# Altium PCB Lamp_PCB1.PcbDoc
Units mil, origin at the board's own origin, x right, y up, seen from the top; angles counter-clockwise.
Board outline 2450 x 1530 mil, 2 copper layers (Top Layer, Bottom Layer); 65 components, 52 nets, 250 pads, 50 vias.
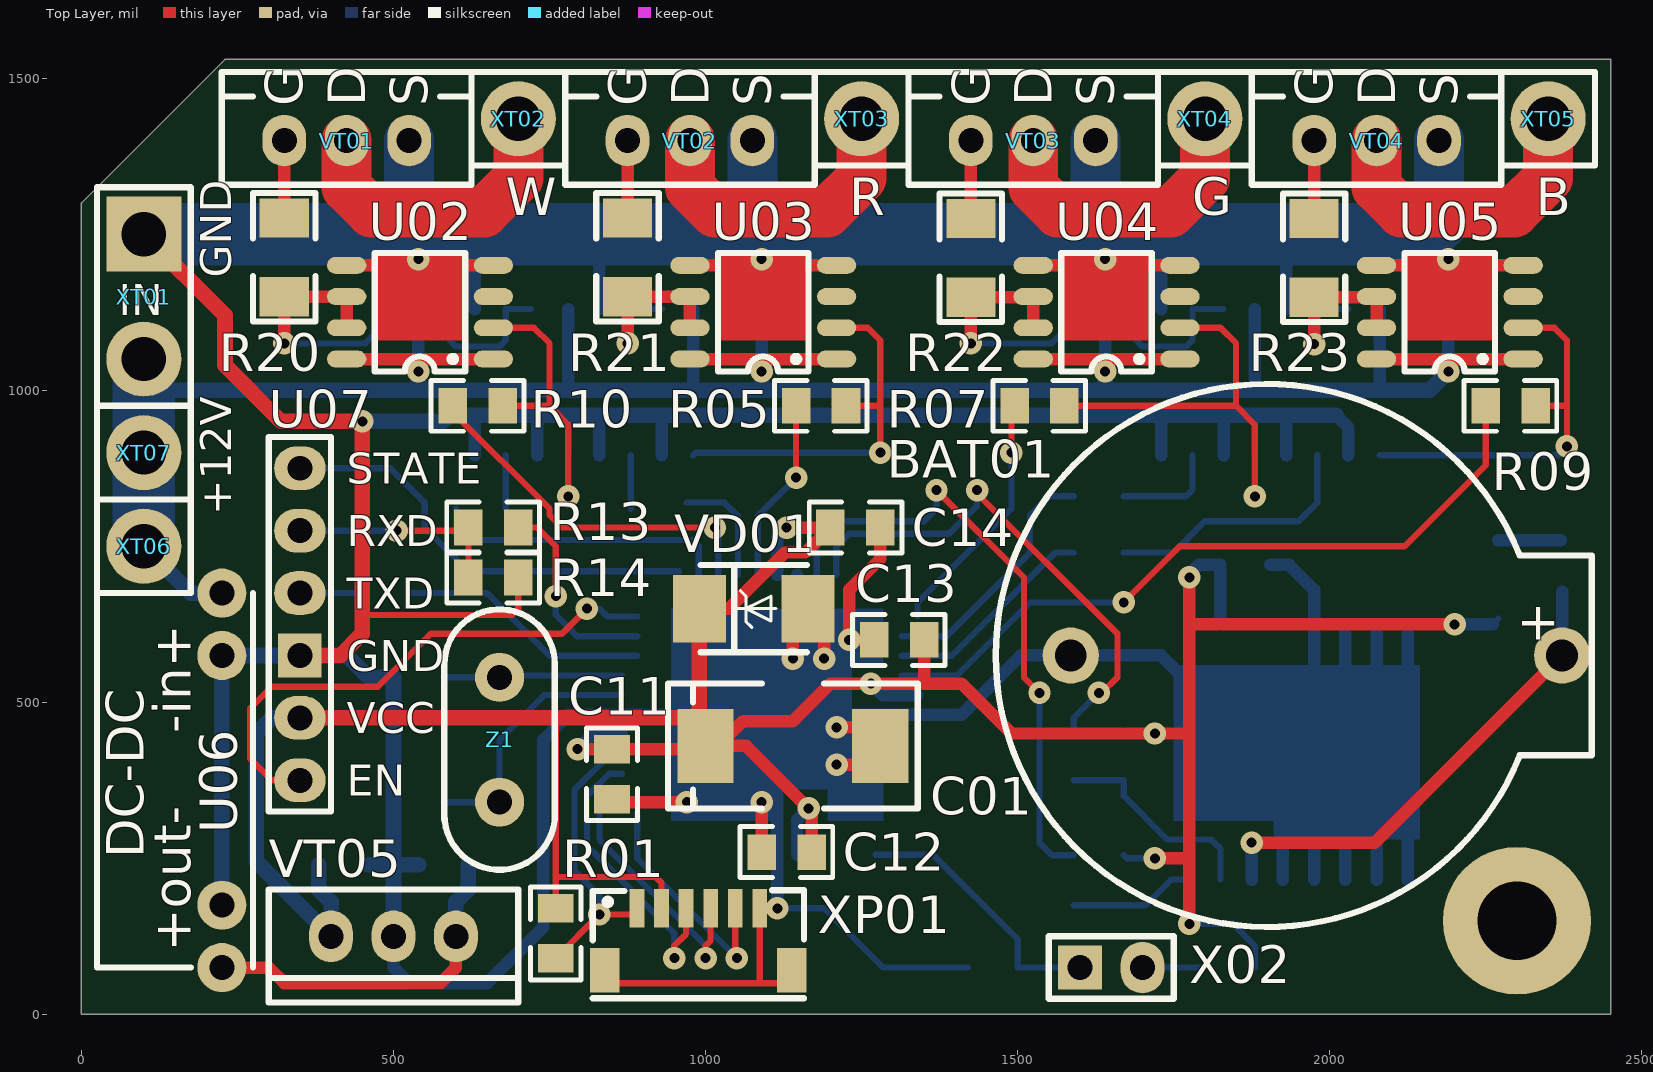
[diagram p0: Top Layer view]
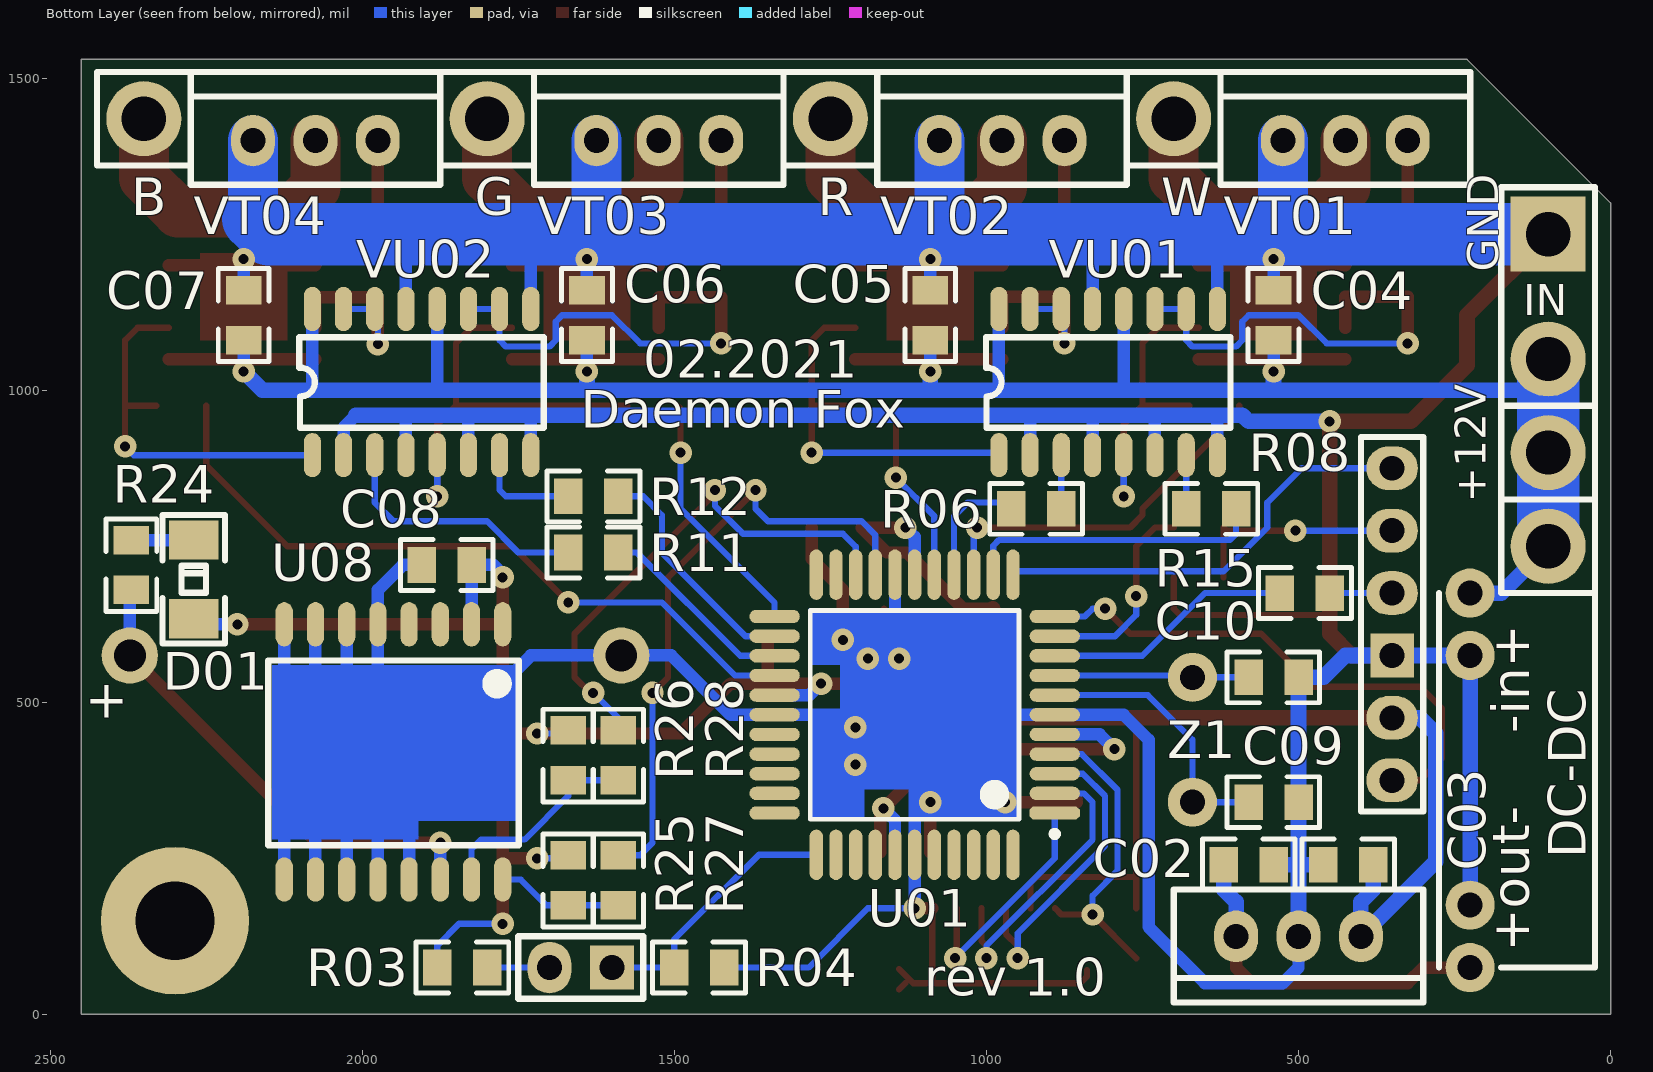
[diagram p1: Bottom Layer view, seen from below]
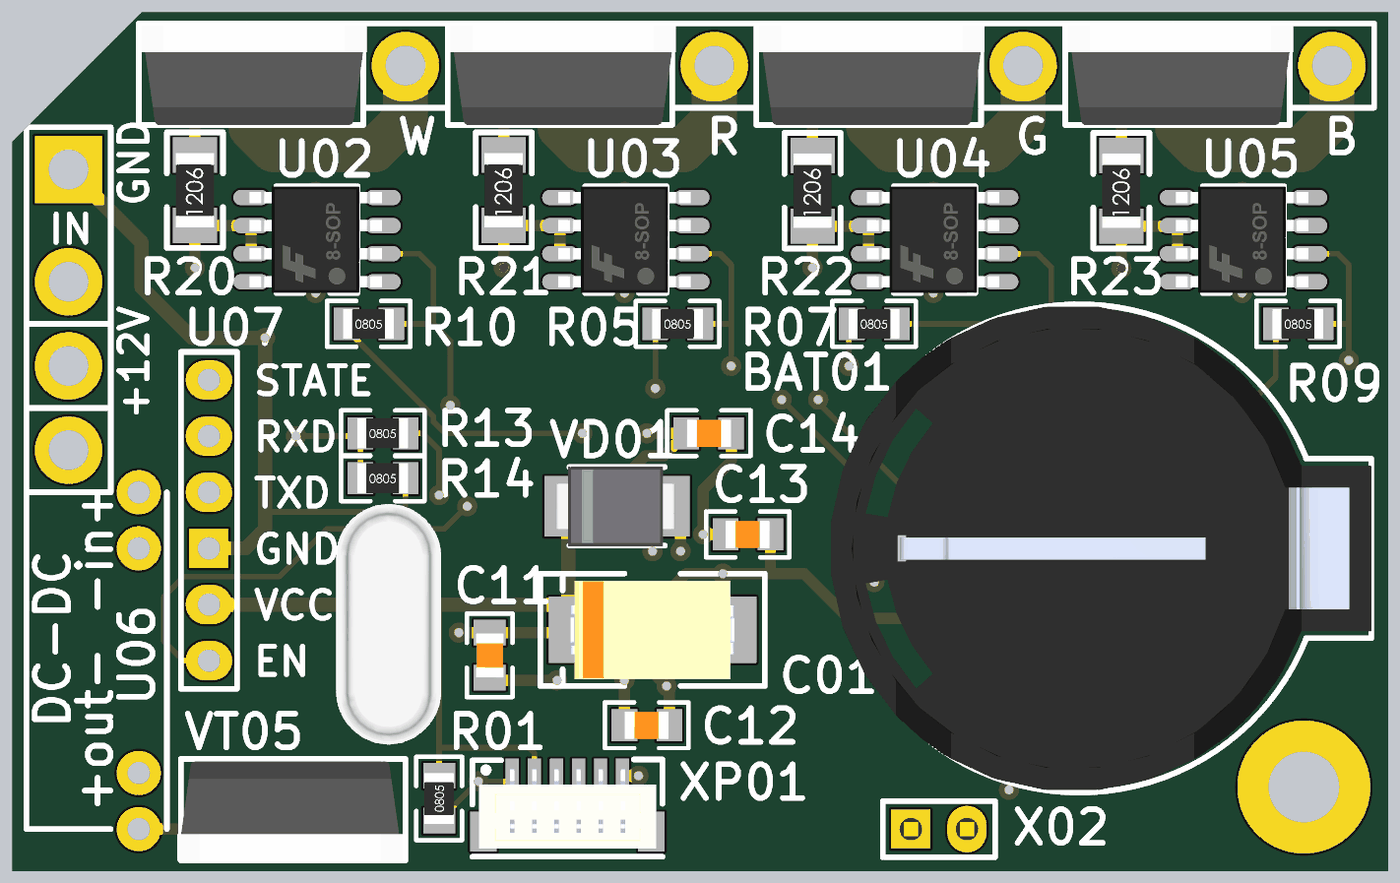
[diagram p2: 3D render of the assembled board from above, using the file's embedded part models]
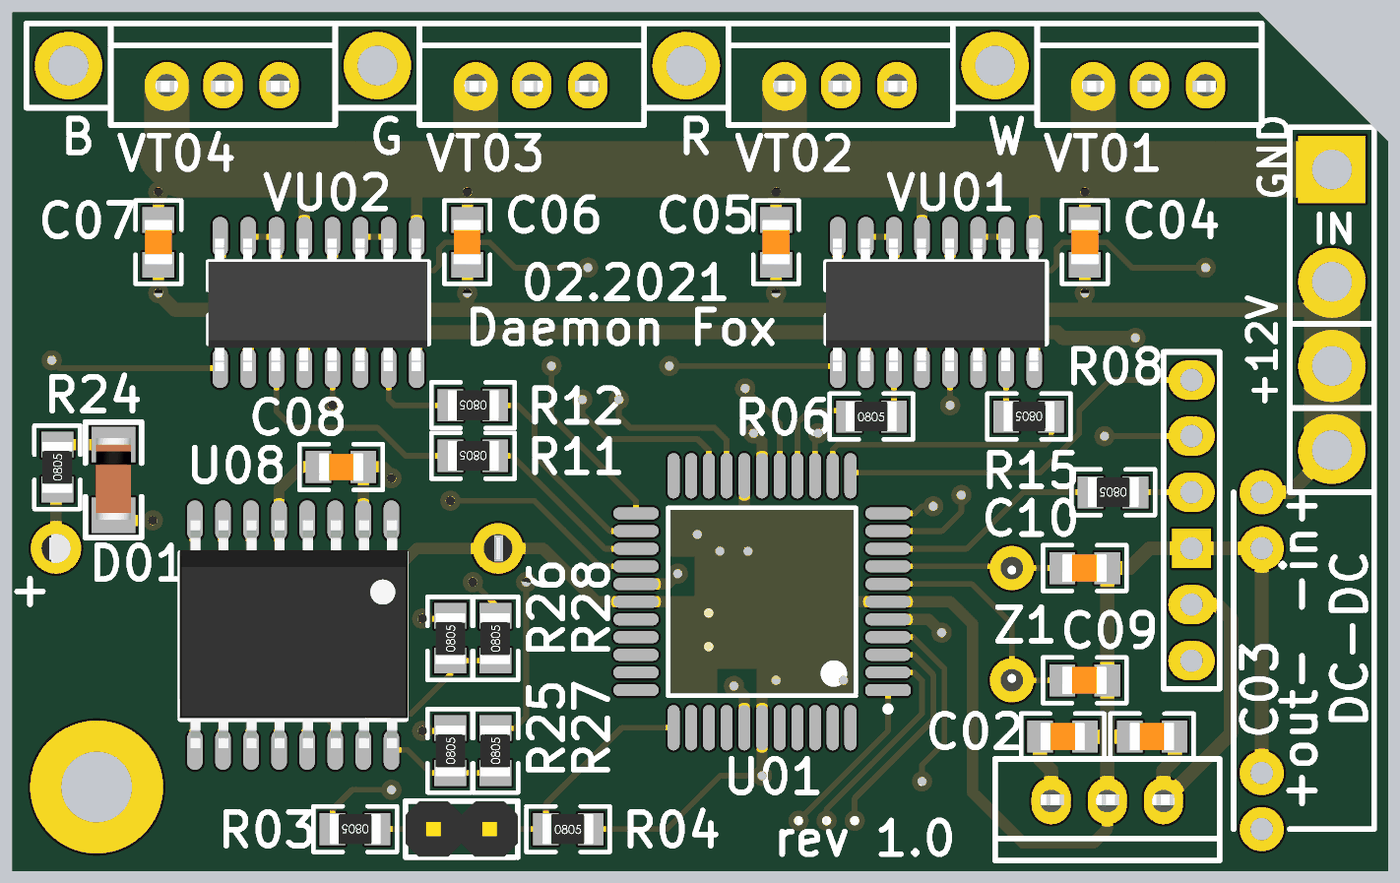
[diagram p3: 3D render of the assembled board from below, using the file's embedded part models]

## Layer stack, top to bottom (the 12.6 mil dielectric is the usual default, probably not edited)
Top Solder: solder mask 0.4, Solder Resist, Dk 3.5
Top Layer: signal copper 1.4
Dielectric 1: dielectric 12.6, FR-4, Dk 4.8
Bottom Layer: signal copper 1.4
Bottom Solder: solder mask 0.4, Solder Resist, Dk 3.5

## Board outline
0,0 0,1300 230,1530 2450,1530 2450,0

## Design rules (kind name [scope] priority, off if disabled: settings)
Clearance [All] p1: gap=10
PolygonConnect [All] p1: connectstyle=Relief reliefconductorwidth=10 reliefentries=4 polygonreliefangle="90 Angle" airgapwidth=10
RoomDefinition Lamp_Sheet1 [InComponentClass('Lamp_Sheet1')] p1: confinementstyle=ConfineIn formatcopy=TRUE lockcomponents=FALSE outline 6045,55 12030,55 12030,745 6045,745
RoutingVias [All] p1: holewidth=28 width=50 viastyle="Through Hole" minholewidth=28 minwidth=50 maxholewidth=28 maxwidth=50
SolderMaskExpansion [All] p1: expansion=4
Width [All] p1: maxlimit=10 minlimit=10 preferedwidth=10
30 further rules are at their usual default settings.

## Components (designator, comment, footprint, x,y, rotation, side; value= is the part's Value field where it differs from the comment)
BAT01 "KLS5-CR2032" KLS5-CR2032 1900,575 r0 top locked
C01 "470uF" cap_tantalum_d 1280,430 r180 top locked
C02 "0.1uF" CAP_0805 540,240 r0 bottom locked
C03 "0.1uF" CAP_0805 460,240 r180 bottom locked
C04 "0.1uF" CAP_0805 540,1160 r270 bottom
C05 "0.1uF" CAP_0805 1090,1160 r270 bottom
C06 "0.1uF" CAP_0805 1640,1160 r270 bottom
C07 "0.1uF" CAP_0805 2190,1160 r270 bottom
C08 "0.1uF" CAP_0805 1825,720 r0 bottom
C09 "22pF" CAP_0805 580,340 r180 bottom locked
C10 "22pF" CAP_0805 580,540 r180 bottom locked
C11 "0.1uF" CAP_0805 850,345 r90 top locked
C12 "0.1uF" CAP_0805 1090,260 r0 top locked
C13 "0.1uF" CAP_0805 1270,600 r0 top
C14 "0.1uF" CAP_0805 1280,780 r180 top
D01 "LL4148" LL4148 2270,643.86 r90 bottom
R01 "10K" RES_0805 760,90 r90 top locked
R03 "10K" RES_0805 1800,75 r0 bottom
R04 "10K" RES_0805 1500,75 r180 bottom
R05 "1.2K" RES_0805 1145,975 r0 top locked
R06 "1.2K" RES_0805 960,810 r180 bottom
R07 "1.2K" RES_0805 1495,975 r0 top locked
R08 "1.2K" RES_0805 600,810 r0 bottom
R09 "1.2K" RES_0805 2250,975 r0 top locked
R10 "1.2K" RES_0805 595,975 r0 top locked
R11 "1.2K" RES_0805 1590,740 r0 bottom
R12 "1.2K" RES_0805 1590,830 r0 bottom
R13 "10K" RES_0805 620,780 r0 top
R14 "10K" RES_0805 620,700 r0 top
R15 "10K" RES_0805 450,675 r0 bottom
R20 "30R" RES_1206 325,1150 r90 top locked
R21 "30R" RES_1206 875,1150 r90 top locked
R22 "30R" RES_1206 1425,1149.02 r90 top locked
R23 "30R" RES_1206 1975,1149.02 r90 top locked
R24 "200R" RES_0805 2370,680 r90 bottom
R25 "4,7K" RES_0805 1670,175 r90 bottom
R26 "4,7K" RES_0805 1670,375 r90 bottom
R27 "560R" RES_0805 1590,175 r90 bottom
R28 "560R" RES_0805 1590,375 r90 bottom
U01 "ATmega16-16AI" My_44A_M 1115,480 r0 bottom locked
U02 "TC4420" ATtiny13A 660,1050 r180 top locked
U03 "TC4420" ATtiny13A 1210,1050 r180 top locked
U04 "TC4420" ATtiny13A 1760,1050 r180 top locked
U05 "TC4420" ATtiny13A 2310,1050 r180 top locked
U06 "Mini-360" Mini-360 225,75 r90 top locked
U07 "HC-06" HC-05/06 350,875 r270 top locked
U08 "DS3231_DUP" DS3231 1775,625 r0 bottom locked
VD01 "SMBJ5.0A" SMBJ5.0A 1164,650 r180 top locked
VT01 "IRF530" "IRF530 - DUP" 525,1400 r90 top locked
VT02 "IRF530" "IRF530 - DUP" 1075,1400 r90 top locked
VT03 "IRF530" "IRF530 - DUP" 1625,1400 r90 top locked
VT04 "IRF530" "IRF530 - DUP" 2175,1400 r90 top locked
VT05 "L7805" L7805 400,125 r270 top locked
VU01 "TLP281-4" TLP281-4 609.1,940 r90 bottom locked
VU02 "TLP281-4" TLP281-4 1709.1,940 r90 bottom locked
X02 "PLS-2" "PLS-2 - DUP" 1600,75 r0 top
XP01 "JST SH 1.0mm_6P" "JST SH 1.0mm 6P" 838.8,70.6 r0 top locked
XT01 "LED_12v_IN" "LED_12v_IN - DUP" 100,1250 r270 top locked
XT02 "LED_12v_1" LED_12v_1 700,1435 r90 top locked
XT03 "LED_12v_1" LED_12v_1 1250,1435 r90 top locked
XT04 "LED_12v_1" LED_12v_1 1800,1435 r90 top locked
XT05 "LED_12v_1" LED_12v_1 2350,1435 r90 top locked
XT06 "LED_12v_1" LED_12v_1 100,750 r0 top locked
XT07 "LED_12v_1" LED_12v_1 100,900 r0 top locked
Z1 "16MHz" QUARTZ 670,340 r180 top locked

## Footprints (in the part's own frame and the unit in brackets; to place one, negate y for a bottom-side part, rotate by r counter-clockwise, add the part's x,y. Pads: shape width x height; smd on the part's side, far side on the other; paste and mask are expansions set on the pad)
ATtiny13A [mil] "ATtiny13A SOP-8"
  oval 63x27 smd: 1(0,0) 2(0,-50) 3(0,-100) 4(0,-150) 5(235,-150) 6(235,-100) 7(235,-50) 8(235,0)
  silkscreen extent 45,-170 190,20, body extent 2,-170 238,20, height 67
CAP_0805 [mm] "CAP 0805 by DFox"
  rect 1.16x1.45 smd: 1(0,0) 2(2.032,0)
  silkscreen extent -0.88,-1.03 2.89,1.04, body extent 0,-0.63 2,0.63, height 0.8
cap_tantalum_d [mil] "capacitor tantalum, Type D"
  rect 90x118 smd: 1(280,0)
  rect 90x118.5 smd: 2(0,0)
  silkscreen extent -60,-100 340,100, body extent -6,-88 286,88, height 118
DS3231 [mm] "Часы реального времени, SO-16W"
  oval 0.7x1.8 smd: 1(0,0) 2(1.27,0) 3(2.54,0) 4(3.81,0) 5(5.08,0) 6(6.35,0) 7(7.62,0) 8(8.89,0) 9(8.89,10.389) 10(7.62,10.389) 11(6.35,10.389) 12(5.08,10.389) 13(3.81,10.389) 14(2.54,10.389) 15(1.27,10.389) 16(0,10.389)
  silkscreen extent -0.66,1.47 9.55,8.99, body extent -0.75,0 9.58,10.31, height 2.48
HC-05/06 [mil] "Bluetooth модуль HC-06 slave; HC-05 master/slave."
  oval 70x82.68 hole 40: 1(0,0) 2(100,0) 3(200,0) 5(400,0) 6(500,0)
  rect 70x70 hole 40: 4(300,0)
  silkscreen extent -50,-50 550,50
"IRF530 - DUP" [mil] "IRF530 N-канал, 100в, 15А, TO-220AB"
  oval 82.68x70 hole 40: 1(0,200) 2(0,100) 3(0,0)
  silkscreen extent -71,-100 110,300, body extent -71,-106 106,295, height 869
"JST SH 1.0mm 6P" [mm] "JST- BM06B-SRSS-TB, 6P"
  rect 0.6x1.55 smd: 1(1.3,2.525) 2(2.3,2.525) 3(3.3,2.525) 4(4.3,2.525) 5(5.3,2.525)
  rect 0.599x1.549 smd: 6(6.301,2.524)
  rect 1.201x1.798 smd: 7(7.6,0)
  rect 1.199x1.798 smd: 8(0,0)
  silkscreen extent -0.5,-1.14 8.1,3.26, body extent -0.19,-0.76 7.81,2.84, height 4.25
KLS5-CR2032 [mil] "Батарейный отсек на 1xCR2032"
  round 90 hole 51.2: 1(472.48,0) 2(-314.92,0)
  silkscreen extent -435,-435 520,435, body extent -445,-433 520,433, height 335
L7805 [mil] "Стабилизатор напряжения +5В, 1.5А, TO-220"
  oval 82.68x70 hole 40: 1(0,200) 2(0,100) 3(0,0)
  silkscreen extent -75,-100 106,300, body extent -71,-106 106,295, height 869
LED_12v_1 [mm]
  round 3.054 hole 1.8: 1(0,0)
  silkscreen extent -1.91,-1.91 1.91,1.91
"LED_12v_IN - DUP" [mm]
  round 3.054 hole 1.8: 1(5.08,0)
  rect 3.054x3.054 hole 1.8: 2(0,0)
  silkscreen extent -1.91,-1.91 6.98,1.91
LL4148 [mm] "Diod SOD80 200mA 100V"
  rect 1.6x2 smd: 1(-0.25,0) 2(2.95,0)
  silkscreen extent -1.26,-1.27 3.97,1.27, body extent -0.45,-0.8 3.25,0.8, height 1.61
Mini-360 [mm] "Mini360, понижающий модуль, с 4,75 в-23 в до 1 В-17 в, 17x11x3,8 мм"
  round 2 hole 1.016: 1(15.24,0) 2(0,0) 3(2.54,0) 3(12.7,0)
  silkscreen extent 0,-1.27 15.24,5.08
My_44A_M [mm]
  oct 2.05x0.544 smd: 1(-5.7,4)
  oval 2.05x0.544 smd: 2(-5.7,3.2) 3(-5.7,2.4) 4(-5.7,1.6) 5(-5.7,0.8) 6(-5.7,0) 7(-5.7,-0.8) 8(-5.7,-1.6) 9(-5.7,-2.4) 10(-5.7,-3.2) 11(-5.7,-4) 23(5.7,-4) 24(5.7,-3.2) 25(5.7,-2.4) 26(5.7,-1.6) 27(5.7,-0.8) 28(5.7,0) 29(5.7,0.8) 30(5.7,1.6) 31(5.7,2.4) 32(5.7,3.2) 33(5.7,4)
  oval 0.544x2.05 smd: 12(-4,-5.7) 13(-3.2,-5.7) 14(-2.4,-5.7) 15(-1.6,-5.7) 16(-0.8,-5.7) 17(0,-5.7) 18(0.8,-5.7) 19(1.6,-5.7) 20(2.4,-5.7) 21(3.2,-5.7) 22(4,-5.7) 34(4,5.7) 35(3.2,5.7) 36(2.4,5.7) 37(1.6,5.7) 38(0.8,5.7) 39(0,5.7) 40(-0.8,5.7) 41(-1.6,5.7) 42(-2.4,5.7) 43(-3.2,5.7) 44(-4,5.7)
  silkscreen extent -5.82,-4.25 4.25,4.97, body extent -5,-5 5,5, height 1.2
"PLS-2 - DUP" [mil]
  rect 70x70 hole 40: 1(0,0)
  oval 70x82.68 hole 40: 2(100,0)
  silkscreen extent -50,-50 150,50, body extent -50,-49 150,49, height 335
QUARTZ [mm] "quartz crystal resonator"
  round 2 hole 1.016: 1(0,0) 2(0,-5.08)
  silkscreen extent -2.25,-7.84 2.25,2.75, body extent -2.33,-7.99 2.33,2.91, height 13.5
RES_0805 [mm] "RES 0805 by DFox"
  rect 1.16x1.45 smd: 1(0,0) 2(2.032,0)
  silkscreen extent -0.88,-1.03 2.89,1.04, body extent -0.15,-0.67 2.15,0.67, height 0.76
RES_1206 [mil] "RES 1206 by DFox"
  rect 63x78.74 smd: 1(0,0) 2(125.98,0)
  silkscreen extent -40,-50 166,50, body extent -3,-34 129,34, height 33
SMBJ5.0A [mil] "TVS SUPRESSOR 5V, [DO-214AA]"
  rect 85x108 smd: 1(0,0) 2(174,0)
  silkscreen extent 2,-70 172,70, body extent -16,-71 196,71, height 93
TLP281-4 [mm] "Оптопара транзисторная [SOP-16]"
  oval 1.8x0.7 smd: 1(-1.118,9.421) 2(-1.118,8.151) 3(-1.118,6.881) 4(-1.118,5.611) 5(-1.118,4.341) 6(-1.118,3.071) 7(-1.118,1.801) 8(-1.118,0.531) 9(4.826,0.531) 10(4.826,1.801) 11(4.826,3.071) 12(4.826,4.341) 13(4.826,5.611) 14(4.826,6.881) 15(4.826,8.151) 16(4.826,9.421)
  silkscreen extent 0,0 3.68,9.95, body extent -1.25,0.05 4.75,9.95, height 1.4

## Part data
BAT01: "Батарейный отсек на 1xCR2032"
C01: library part "470uF 10v_D", "CAPACITOR Tantalium Type D 470uF 10v"
C02 C03 C04 C05 C06 C07 C08 C09 C10 C11 C12 C13 C14: library part "CAP 0805", "CAP 0805 SMD"
D01: "Diod SOD80 200mA 100V"
R01 R03 R04 R05 R06 R07 R08 R09 R10 R11 R12 R13 R14 R15 R24 R25 R26 R27 R28: library part "RES 0805", "RES 0805"
R20 R21 R22 R23: library part "RES 1206", "RES 1206 by DFox"
U01: "AVR 16K Bytes of In-System Programmable Flash Memory"
U02 U03 U04 U05: "HIGH-SPEED MOSFET  DRIVERS"
U06: "Mini360, понижающий модуль, с 4,75 в-23 в до 1 В-17 в, 17x11x3,8 мм"
U07: library part HC-05/06, "Bluetooth модуль HC-06 slave; HC-05 master/slave."
U08: "Часы реального времени"
VD01: "Защитный диод, 500Вт, 5В, [DO-214AA]"
VT01 VT02 VT03 VT04: "IRF530 N-канал, 100в, 15А, TO-220AB"
VT05: "Стабилизатор напряжения +5В, 1.5А, TO-220"
XP01: "JST SH 1.0mm 6P"
Z1: library part QUARTZ, "quartz crystal resonator"

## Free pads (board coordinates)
  round 237 hole 126: 8(2300,150)

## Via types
v1: diameter 36, hole 16, Top Layer to Bottom Layer, tented both sides, 50 vias

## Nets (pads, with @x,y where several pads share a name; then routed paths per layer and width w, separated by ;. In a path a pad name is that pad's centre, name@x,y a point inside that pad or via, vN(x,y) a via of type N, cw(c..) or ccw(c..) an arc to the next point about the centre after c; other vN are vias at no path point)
GND: BAT01.2 C01.2 C02.1 C03.1 C04.1 C05.1 C06.1 C07.1 C08.2 C09.2 C10.2 C11.1 C12.1 C13.1 C14.1 R04.2 R14.2 U01.6 U01.18 U01.28 U01.39 U02.4 U02.5 U03.4 U03.5 U04.4 U04.5 U05.4 U05.5 U06.3 U07.4 U08.5 U08.6 U08.7 U08.8 U08.9 U08.10 U08.11 U08.12 U08.13 VD01.1 VT01.3 VT02.3 VT03.3 VT04.3 VT05.2 VU01.2 VU01.4 VU01.6 VU01.8 VU01.9 VU01.13 VU02.2 VU02.4 VU02.6 VU02.8 VU02.9 VU02.13 XP01.6 XP01.7 XP01.8 XT01.2 | length 13135.7
  Top Layer w10: 450,640 690,640 700,650 R14.2 ; XP01.8 838.8,61.2 850,50 1086.87,50 ; C11.1 C11.1@855,340 ; XP01.6 1086.87,50 ; XP01.7@1130,50 XP01.7@1140,40 ; XP01.7@1140,72.58 XP01.7 1117.42,50 1086.87,50 ; VD01.1@1140,626 VD01.1 VD01.1@1190,624 ; C01.2@1250,400 C01.2 C01.2@1250,460
  Top Layer w20: U02.5 U02.4 ; C11.1@855,340 v1(970,340) ; U03.5 U03.4 ; XP01.6 v1(1115,170) ; C12.1 v1(1090,340) ; v1(1140,570) VD01.1@1140,626 ; v1(1190,570) VD01.1@1190,624 ; v1(1210,400) C01.2@1250,400 ; v1(1210,460) C01.2@1250,460 ; C13.1 v1(1230,600) 1230,680 1280,730 C14.1 ; U04.5 U04.4 ; U05.5 U05.4
  Top Layer w25: XT01.2 230,1120 230,1040 320,950 v1(450,950) 450,640 450,610 415,575 U07.4
  Bottom Layer w10: 624,1250 630,1244 ; 825,1250 830,1245 ; v1(1115,170) 1190,170 1285,75 R04.2 ; 1725,1250 1730,1245
  Bottom Layer w20: VT05.2 500,75 525,50 650,50 740,140 740,440 780,480 U01.6@865.59,480 ; C04.1 v1(540,1210) ; VU01.8 630,960 ; VU01.9 630,1244 ; VU01.6 730,960 ; VU01.4 830,960 ; VU01.13 830,1245 ; U01.6@869.09,480 960,480 ; VU01.2 930,960 ; C05.1 v1(1090,1210) ; v1(1115,170) U01.39 1115,330 ; 1146.5,631.5 U01.18 ; 1260,480 U01.28 1410,480 1505,575 BAT01.2 1730,575 1762.5,542.5 ; C06.1 v1(1640,1210) ; VU02.8 1730,960 ; VU02.9 1730,1245 ; VU02.6 1830,960 ; C08.2 1935,720 1975,680 U08.5 1975,525 ; U08.13 1925,315 ; VU02.4 1930,960 ; VU02.13 1930,1250 ; U08.12 1975,315 ; 2010,960 2030,940 VU02.2 ; U08.11 2025,315 ; 2025,525 U08.6 ; U08.10 2075,315 ; 2075,525 U08.7 ; U08.9 2125,315 ; 2125,525 U08.8 ; C07.1 v1(2190,1210)
  Bottom Layer w25: U06.3@225,175 225,575 U07.4 425,575 460,540 C10.2 C09.2 500,240 ; v1(450,950) 580,950 590,960 630,960 730,960 830,960 930,960 1730,960 1830,960 1930,960 2010,960 ; C03.1 500,240 ; VT05.2 500,240 ; C02.1 500,240
  Bottom Layer w80: 525,1250 VT01.3 ; 1075,1250 VT02.3 ; 1625,1250 VT03.3 ; 2175,1275 VT04.3
  Bottom Layer w100: XT01.2 525,1250 ; 540,1250 624,1250 825,1250 1075,1250 1625,1250 1725,1250 1930,1250 2150,1250 2175,1275
NetBAT01_1: BAT01.1 R24.1 U08.14 | length 786.8
  Top Layer w20: v1(1875,275) 2072.48,275 BAT01.1
  Bottom Layer w10: R24.1 R24.1@2372.48,677.52
  Bottom Layer w20: U08.14 v1(1875,275) ; BAT01.1 R24.1@2372.48,677.52
NetC01_1: C01.1 C03.2 C08.1 C11.2 C12.2 C13.2 C14.2 D01.1 R01.2 R03.2 R25.2 R26.2 U01.5 U01.17 U01.27 U01.38 U07.5 U08.2 VD01.2 VT05.3 XP01.2 | length 5520.2
  Top Layer w10: R01.2 760,220 ; 760,475 760,220 ; XP01.2 929.37,210.63 920,220 760,220 ; C01.1@990,440 C01.1 ; C01.1@995,425 C01.1 ; C01.1@1020,430 C01.1 ; v1(1165,330) v1@1170,325
  Top Layer w20: v1(795,425) C11.2 C01.1@995,425 ; VD01.2 1037.5,650 1127.5,740 1160,740 C14.2 v1(1130,780) ; v1(1165,330) 1065,430 1020,430 1060,470 1140,470 1200,530 v1(1265,530) 1350,530 ; C12.2 v1@1170,325 ; C13.2 1350,530 ; v1(1720,250) 1775,250 ; v1(1775,145) 1775,250 ; v1(1775,700) 1775,625 ; v1(2200,625) 1775,625 ; 1350,530 1410,530 1490,450 v1(1720,450) 1775,450 ; 1775,250 1775,450 ; 1775,450 1775,625
  Top Layer w25: U07.5 760,475 C01.1@980,475 ; C01.1@990,440 VD01.2
  Bottom Layer w10: R25.2 1675,250 v1(1720,250) ; R26.2 1675,450 v1(1720,450) ; v1(1775,145) 1845,145 1880,110 R03.2 ; v1(1775,700) v1@1775,705 ; D01.1@2260.98,625 D01.1
  Bottom Layer w20: v1(795,425) 818.5,448.5 U01.5@865.59,448.5 ; U01.17 1115,765 v1(1130,780) ; U01.38 1146.5,311.5 v1(1165,330) ; v1(1265,530) 1283.5,511.5 U01.27 ; v1@1775,705 1790,720 C08.1 U08.2 ; v1(2200,625) D01.1@2260.98,625
  Bottom Layer w25: U07.5 305,475 280,450 280,245 VT05.3 400,180 380,200 C03.2
NetC02_2: C02.2 U06.2 VT05.1 | length 569
  Top Layer w20: U06.2 300,75 325,50 575,50 600,75 VT05.1
  Bottom Layer w25: VT05.1 600,180 620,200 C02.2
NetC04_2: C04.2 C05.2 C06.2 C07.2 U02.1 U02.8 U03.1 U03.8 U04.1 U04.8 U05.1 U05.8 U06.1 VU01.12 VU01.16 VU02.12 VU02.16 XT01.1 XT06.1 XT07.1 | length 4296.8
  Top Layer w20: U02.8 U02.1 ; U03.8 U03.1 ; U04.8 U04.1 ; U05.8 U05.1
  Bottom Layer w10: 225,995 230,1000 ; 775,1000 780,1005 ; 975,1000 980,1005 ; 1875,1000 1880,1005
  Bottom Layer w20: v1(540,1030) C04.2 ; 780,1005 VU01.12 ; 980,1005 VU01.16 ; v1(1090,1030) C05.2 ; v1(1640,1030) C06.2 ; 1880,1005 VU02.12 ; 2080,1000 VU02.16 ; v1(2190,1030) C07.2
  Bottom Layer w25: XT06.1 175,675 U06.1 ; XT01.1@125,1000 230,1000 540,1000 ; v1(540,1030) 540,1000 ; v1(1090,1030) 1090,1000 ; v1(1640,1030) 1640,1000 ; v1(2190,1030) 2160,1000 2080,1000 1875,1000 1640,1000 ; 540,1000 775,1000 975,1000 1090,1000 ; 1090,1000 1640,1000
  Bottom Layer w100: XT06.1 XT07.1 XT01.1
NetC09_1: C09.1 U01.7 Z1.1 | length 415.2
  Bottom Layer w10: C09.1 Z1.1 670,440 741.5,511.5 U01.7@865.59,511.5
NetC10_1: C10.1 U01.8 Z1.2 | length 286.8
  Bottom Layer w10: C10.1 Z1.2 672.99,542.99 U01.8@865.59,542.99
NetD01_2: D01.2 R24.2 | length 100
  Bottom Layer w20: D01.2 R24.2
NetR01_1: R01.1 U01.4 XP01.1 | length 478.9
  Top Layer w10: R01.1 v1(830,160) 880,160 XP01.1
  Bottom Layer w10: v1(830,160) 830,190 790,230 790,360 847.01,417.01 U01.4@865.59,417.01
NetR03_1: R03.1 X02.2 | length 100
  Bottom Layer w10: X02.2 R03.1
NetR04_1: R04.1 U01.34 X02.1 | length 428.7
  Bottom Layer w10: U01.34 1364.41,255.59 1500,120 R04.1 X02.1
NetR05_1: R05.1 U01.16 | length 300.2
  Top Layer w10: v1(1145,860) 1145,965 1150,970 R05.1
  Bottom Layer w10: U01.16 1083.5,798.5 v1(1145,860)
NetR05_2: R05.2 U03.2 VU01.1 | length 614.9
  Top Layer w10: U03.2 1260,1100 1280,1080 1280,975 ; R05.2 1280,975 ; v1(1280,900) 1280,975
  Bottom Layer w10: VU01.1 984,900 v1(1280,900)
NetR06_1: R06.1 U01.15 | length 184.7
  Bottom Layer w10: R06.1@970,820 1030,820 1052.01,797.99 U01.15
NetR06_2: R06.2 VU01.3 | length 86
  Bottom Layer w10: R06.2 VU01.3
NetR07_1: R07.1 U01.23 | length 401.7
  Top Layer w10: v1(1490,900) 1490,970 R07.1
  Bottom Layer w10: U01.23 1339.41,660 ; 1340,660 1490,810 v1(1490,900)
NetR07_2: R07.2 U04.2 VU02.5 | length 698.8
  Top Layer w10: R07.2 1850,975 ; U04.2 1825,1100 1850,1075 1850,975 ; v1(1880,830) 1880,945 1850,975
  Bottom Layer w10: v1(1880,830) VU02.5
NetR08_1: R08.1 U01.13 | length 483.5
  Bottom Layer w10: R08.1 600,770 610,760 980,760 989.02,750.98 U01.13
NetR08_2: R08.2 VU01.7 | length 86
  Bottom Layer w10: R08.2 VU01.7
NetR09_1: R09.1 U01.26 | length 1170.2
  Top Layer w10: v1(1670,660) 1760,750 2120,750 2250,880 R09.1
  Bottom Layer w10: U01.26@1314.41,542.99 U01.26 1402.99,542.99 1520,660 v1(1670,660)
NetR09_2: R09.2 U05.2 VU02.1 | length 604.1
  Top Layer w10: U05.2 2360,1100 2380,1080 2380,975 ; R09.2 2380,975 ; v1(2380,910) 2380,975
  Bottom Layer w10: VU02.1 2366,896 v1(2380,910)
NetR10_1: R10.1 U01.14 | length 590.4
  Top Layer w10: R10.1 595,965 750,810 750,800 770,780 v1(1015,780)
  Bottom Layer w10: v1(1015,780) 1020.51,774.49 U01.14
NetR10_2: R10.2 U02.2 VU01.5 | length 498.8
  Top Layer w10: U02.2 725,1100 750,1075 750,975 ; R10.2 750,975 ; v1(780,830) 780,945 750,975
  Bottom Layer w10: v1(780,830) VU01.5
NetR11_1: R11.1 U01.25 | length 344.1
  Bottom Layer w10: U01.25@1314.41,574.49 U01.25 1394.49,574.49 1560,740 R11.1
NetR11_2: R11.2 VU02.3 | length 419.1
  Bottom Layer w10: R11.2 1750,740 1800,790 1950,790 1980,820 VU02.3
NetR12_1: R12.1 U01.24 | length 403.5
  Bottom Layer w10: U01.24@1314.41,605.98 U01.24 1385.98,605.98 1520,740 1520,800 1550,830 R12.1
NetR12_2: R12.2 VU02.7 | length 170.1
  Bottom Layer w10: R12.2 1770,830 1780,840 VU02.7
NetR13_1: R13.1 R14.1 U07.2 | length 352.1
  Top Layer w10: v1(505,775) 615,775 R13.1 R14.1
  Bottom Layer w10: U07.2 v1(505,775)
NetR13_2: R13.2 U01.10 | length 327.1
  Top Layer w10: R13.2 730,780 760,750 v1(760,670)
  Bottom Layer w10: v1(760,670) 760,640 794.02,605.98 U01.10
NetR15_1: R15.1 U07.3 | length 100
  Bottom Layer w10: U07.3 R15.1
NetR15_2: R15.2 U01.9 | length 402.2
  Bottom Layer w10: R15.2 650,675 750.51,574.49 U01.9
NetR20_1: R20.1 U02.6 U02.7 VU01.10 VU01.11 | length 731.1
  Top Layer w20: v1(325,1075) R20.1 U02.6 U02.7
  Bottom Layer w10: v1(325,1075) 455,1075 500,1120 580,1120 590,1110 590,1080 600,1070 670,1070 680,1080 VU01.10 VU01.11@720,1130
NetR20_2: R20.2 VT01.1 | length 124
  Top Layer w20: R20.2 VT01.1
NetR21_1: R21.1 U03.6 U03.7 VU01.14 VU01.15 | length 339.1
  Top Layer w20: v1(875,1075) R21.1 U03.6 U03.7
  Bottom Layer w10: v1@870,1080 v1(875,1075) 875,1125 VU01.14 VU01.15
NetR21_2: R21.2 VT02.1 | length 124
  Top Layer w20: R21.2 VT02.1
NetR22_1: R22.1 U04.6 U04.7 VU02.10 VU02.11 | length 739.5
  Top Layer w10: R22.1 R22.1@1425,1150 ; U04.6@1524.02,1149.02 U04.6@1525,1148.04
  Top Layer w20: v1(1425,1075) R22.1 U04.6@1524.02,1149.02 ; U04.7 U04.6@1525,1148.04
  Bottom Layer w10: v1(1425,1075) 1555,1075 1600,1120 1680,1120 1690,1110 1690,1080 1700,1070 1770,1070 1780,1080 VU02.10 VU02.11
NetR22_2: R22.2 VT03.1 | length 125
  Top Layer w20: R22.2 VT03.1
NetR23_1: R23.1 U05.6 U05.7 VU02.14 VU02.15 | length 323.4
  Top Layer w10: U05.6@2074.02,1149.02 U05.6@2075,1148.04
  Top Layer w20: v1(1975,1074.02) R23.1 U05.6@2074.02,1149.02 ; U05.7 U05.6@2075,1148.04
  Bottom Layer w10: v1(1975,1074.02) VU02.14@1975,1124.02 ; VU02.14 VU02.15
NetR23_2: R23.2 VT04.1 | length 125
  Top Layer w20: R23.2 VT04.1
NetR25_1: R25.1 R27.1 U08.16 | length 207.6
  Bottom Layer w10: R27.1 R25.1 1705,175 1746,216 U08.16 U08.16@1771,220
NetR26_1: R26.1 R28.1 U08.15 | length 344.2
  Bottom Layer w10: R28.1 R26.1 1670,350 1740,280 1810,280 1825,265 U08.15
NetR27_2: R27.2 U01.19 | length 1012.8
  Top Layer w10: v1(1370,840) 1510,700 1510,540 v1(1535,515) v1@1535,528.19
  Bottom Layer w10: U01.19 1177.99,767.99 1200,790 1350,790 1370,810 v1(1370,840) ; v1(1535,515) 1535,275 1555,255 R27.2
NetR28_2: R28.2 U01.20 | length 839.9
  Top Layer w10: v1(1435,840) 1430,840 1660,610 1660,540 1635,515 v1(1630,515)
  Bottom Layer w10: U01.20 1209.49,749.49 1230,770 1390,770 1435,815 v1(1435,840) ; R28.2 1590,475 v1(1630,515)
NetU01_1: U01.1 XP01.5 | length 365.3
  Top Layer w10: XP01.5 1047.48,92.52 v1(1050,90)
  Bottom Layer w10: U01.1 890.59,250 v1@1040.3,100.3
NetU01_2: U01.2 XP01.4 | length 445.2
  Top Layer w10: v1(1000,90) 1000,110 1008.11,118.11 XP01.4
  Bottom Layer w10: U01.2@865.59,354.02 844.02,354.02 830,340 830,280 1000,110 v1(1000,90)
NetU01_3: U01.3 XP01.3 | length 476.1
  Top Layer w10: v1(950,90) 950,110 968.74,128.74 XP01.3
  Bottom Layer w10: U01.3@865.59,385.51 845.51,385.51 810,350 810,270 950,130 v1(950,90)
NetU01_11: U01.11 U07.6 | length 866.5
  Top Layer w10: U07.6 305,375 270,410 270,490 305,525 475,525 560,610 770,610 v1(810,650)
  Bottom Layer w10: v1(810,650) 830,650 842.52,637.48 U01.11
NetU01_12: U01.12 U07.1 | length 699.3
  Bottom Layer w10: U07.1 495,875 550,820 550,780 620,710 U01.12@957.52,710
NetVT01_2: VT01.2 XT02.1 | length 484.4
  Top Layer w80: VT01.2 425,1325 465,1285 645,1285 700,1340 XT02.1
NetVT02_2: VT02.2 XT03.1 | length 484.4
  Top Layer w80: VT02.2 975,1325 1015,1285 1195,1285 1250,1340 XT03.1
NetVT03_2: VT03.2 XT04.1 | length 484.4
  Top Layer w80: VT03.2 1525,1325 1565,1285 1745,1285 1800,1340 XT04.1
NetVT04_2: VT04.2 XT05.1 | length 484.4
  Top Layer w80: VT04.2 2075,1325 2115,1285 2295,1285 2350,1340 XT05.1
pads on no net: U01.21 U01.22 U01.29 U01.30 U01.31 U01.32 U01.33 U01.35 U01.36 U01.37 U01.40 U01.41 U01.42 U01.43 U01.44 U02.3 U03.3 U04.3 U05.3 U08.1 U08.3 U08.4

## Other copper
Top Layer:
  region net GND: 470,1220 470,1080 610,1080 610,1220
  region net GND: 2120,1220 2120,1080 2260,1080 2260,1220
  region net GND: 1570,1220 1570,1080 1710,1080 1710,1220
  region net GND: 1020,1220 1020,1080 1160,1080 1160,1220
Bottom Layer:
  rectangle net GND: 1910,280 2145,560
  rectangle net GND: 1750,310 1995,560
  region net GND: 1285,560 1285,650 1225,650 1225,560
  region net GND: 1235,650 945,650 945,360 1235,360
  region net GND: 1285,310 1285,490 1195,490 1195,310
  region net GND: 1125,310 1125,380 945,380 945,310

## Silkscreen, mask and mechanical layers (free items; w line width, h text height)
Top Overlay:
  text "W" at 680,1280 h60
  text "R" at 1230,1280 h60
  text "G" at 1780,1280 h60
  text "B" at 2330,1280 h60
Bottom Overlay:
  text "W" at 720,1280 h60
  text "R" at 1270,1280 h60
  text "G" at 1820,1280 h60
  text "B" at 2370,1280 h60
  text "02.2021" at 1550,1020 h60
  text "Daemon Fox" at 1650,940 h60
  text "rev 1.0" at 1100,30 h60
Mechanical 3:
  the board outline again, w10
